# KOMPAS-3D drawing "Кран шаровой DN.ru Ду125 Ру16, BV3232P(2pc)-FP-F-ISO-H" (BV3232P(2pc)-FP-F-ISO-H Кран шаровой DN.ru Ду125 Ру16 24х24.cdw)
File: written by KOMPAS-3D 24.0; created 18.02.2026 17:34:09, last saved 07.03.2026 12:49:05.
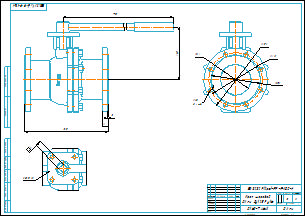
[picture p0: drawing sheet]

Document properties: Автор: R2D2; Форматы листов документа: A2; Полное имя файла: BV3232P(2pc)-FP-F-ISO-H Кран шаровой DN.ru Ду125 Ру16 24х24.m3d; Масса: 32; Наименование: Кран шаровой DN.ru Ду125 Ру16; Количество листов документа: 1; Примечание: D160-74641

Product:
- Part/product: Кран шаровой DN.ru Ду125 Ру16  | designation BV3232P(2pc)-FP-F-ISO-H
    Масса: 32
    Раздел спецификации: Прочие изделия
    Примечание: D160-74641

Views: Проекционный вид 2, Проекционный вид 3
Referenced files in E:\Работа\Зайцев\BV3232P(2pc)-FP-F-ISO-H Кран шаровой DN.ru Ду15-300 Ру16-40\DN125 PN16\: BV3232P(2pc)-FP-F-ISO-H Кран шаровой DN.ru Ду125 Ру16.m3d
Referenced files in E:\Работа\Зайцев\Для компаса\: чертеж DN.ru А3.cdt
Referenced files in E:\Работа\Зайцев\BV3232P(2pc)-FP-F-ISO-H Кран шаровой DN.ru Ду15-300 Ру16-40\DN125 PN16 24х24\: BV3232P(2pc)-FP-F-ISO-H Кран шаровой DN.ru Ду125 Ру16 24х24.m3d
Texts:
  BV3232P(2pc)-FP-F-ISO-H
  ISO 5211
  чертеж DN.ru А3.cdt
  Кран шаровой
  DN.ru Ду125 Ру16
  Кран шаровой DN.ru Ду125 Ру16
  BV3232P(2pc)-FP-F-ISO-H Кран шаровой DN.ru Ду125 Ру16
Dimensions and other numbers on the sheet: 0; 3; 4; 250; 210; 190; 122; 18; 8 отв.; 24; 1:2; 1; 2; 32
